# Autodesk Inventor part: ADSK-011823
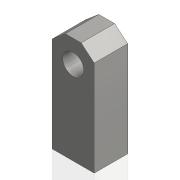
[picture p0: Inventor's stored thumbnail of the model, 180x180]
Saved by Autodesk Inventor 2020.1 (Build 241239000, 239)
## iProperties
Created: 1999-12
Part Number: ADSK-011823
Material: Aluminum
Description: PLT-02,FH,CP,07,010,025,9E,MNT,CYLINDER
Document SubType Name: Modeling
Designer: sspink
Density: 2.71 g/cm^3
Appearance: Steel
Mass: 69.3849 g
Surface Area: 80.253 cm^2
Volume: 25.6033 cm^3
Control State: 0
Master: False
Checked Out: False
Shininess: 0.0
Length Units: 11269
Angle Units: 11279
Time Units: 11290
Mass Units: 11283
Length Display Precision: 3
Angle Display Precision: 2
Compacted: True
Material Desc: FLAT,HRS,0.750 X 1.00
Cutlength: 2.5
Material_number: A084389
Dimensions: 25x63,5x20 mm
Mass: 0,069 kg
DocNumber: ADSK-011823.ipt
Folder: 01 - Themengebiete\Simplification\01 - Packaging machine\
VDS_Category: 3D Komponenten
Density: 0.0
Volumn: 0.0
Area: 0.0
PropertySet Name: Model Information
Author: sspink
Revision Number: -
Title: PLT-02,FH,CP,07,010,025,9E,MNT,CYLINDER
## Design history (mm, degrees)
node "Hole1" dims "d8" = 10.106, "d9" = 9.525, "d10" = 6.35, "d11" = 60 deg, "d12" = 32.3, "d13" = 118 deg, "d14" = 24
node "Solide1"
  node "Extrusion1" dims "d6" = 20, "d7" = 0
sketch "Sketch1"
  geometry: L1 (-12.5, -50)-(12.5, -50); L2 (12.5, -50)-(12.5, 13.5); L3 (12.5, 13.5)-(-12.5, 13.5); L4 (-12.5, 13.5)-(-12.5, -50); L5 (0, -50)-(0, 0); L6 (4.717, 13.5)-(12.5, 6.946); L7 (-12.5, 6.946)-(-4.717, 13.5); C1 r 6.25 at (0, 0); A1 r 14.3 centre (0, 0) between (4.717, 13.5) and (12.5, 6.946); 1 further point
  constraints: 14 end point, 4 point on circle, 4 point on line, 3 parallel, 2 centre point, 2 coincident, 1 horizontal, 1 midpoint, 1 perpendicular, 1 vertical alignment
  dimensions: "d0" = 63.5 distance of L1.end L2.end; "d1" = 25 distance of L1.start L1.end; "d3" = 12.5 diameter of C1; "d4" = 50 distance of L5.start L5.end; "d5" = 28.6004 diameter of A1
node "Corps solides"
node "Corps surfaciques"
sketch "Sketch2"
  geometry: L1 (25, 20)-(0, 20) reference; L2 (0, 0)-(0, 20) reference; L3 (0, 0)-(25, 0) reference; L4 (25, 0)-(25, 20) reference; L5 (0, 10)-(25, 10); L6 (12.5, 20)-(12.5, 0); 1 further point
  constraints: 5 midpoint, 4 end point
